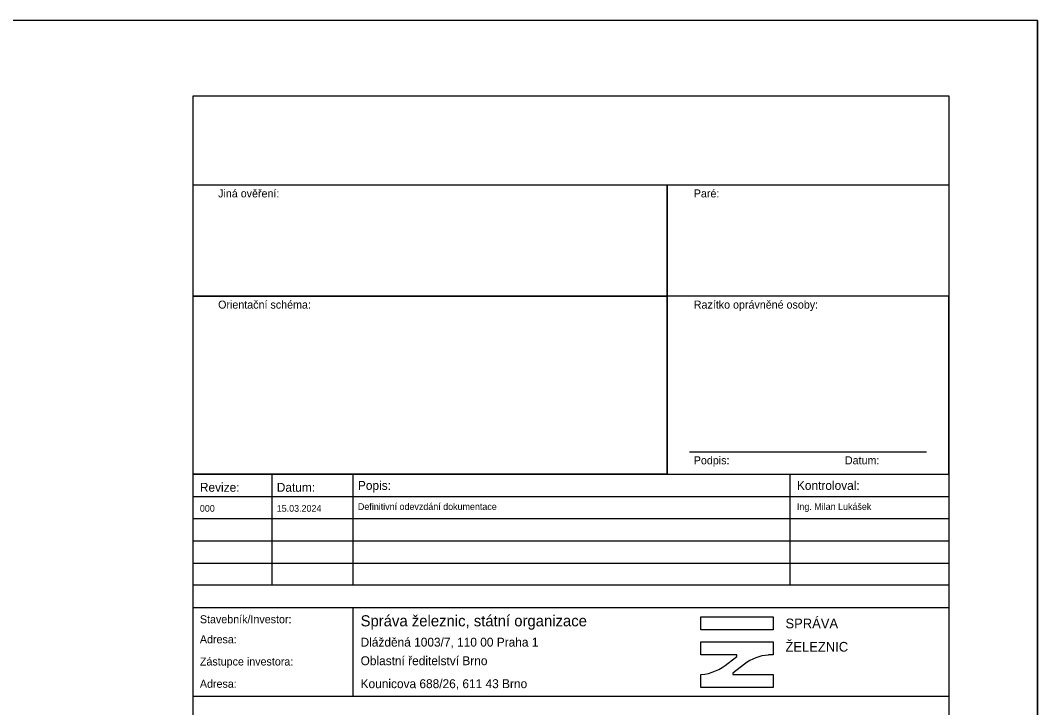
# Model space of a CAD drawing. Extents: x 2343 to 7744, y -5890 to 2050.
# Drawn here: x 6651.2 to 6880, y -5747.5 to -5593 of the extents above; entities that cross this region are included whole.
import ezdxf

# ---------------------------------------------------------------- set-up
doc = ezdxf.new("R2010")
doc.units = 0
for name, color, linetype in [('Default', 7, 'Continuous'), ('Rozpiska_Logo', 7, 'Continuous'), ('Rozpiska_pola_3', 7, 'Continuous'), ('Rozpiska_pole_1', 7, 'Continuous'), ('Rozpiska_pole_2', 7, 'Continuous'), ('Rozpiska_pole_4', 7, 'Continuous'), ('Rozpiska_pole_5', 7, 'Continuous'), ('Rozpiska_pole_6', 7, 'Continuous'), ('Vrstva 50', 7, 'Continuous')]:
    doc.layers.add(name, color=color, linetype=linetype)

msp = doc.modelspace()

# ---------------------------------------------------------------- linework, layer by layer
at = {"layer": 'Default'}
for p, q in [((6880, -5593), (6880, -5890)), ((6796.65, -5695), (6796.65, -5630))]:
    msp.add_line(p, q, dxfattribs=at)
at = {"layer": 'Rozpiska_Logo'}
for p, q in [((6810.4, -5737.47), (6812.34, -5736.01)), ((6812.34, -5736.01), (6812.34, -5735.66)), ((6814.03, -5737.74), (6811.42, -5739.76)), ((6811.42, -5739.76), (6811.42, -5740.07))]:
    msp.add_line(p, q, dxfattribs=at)
msp.add_lwpolyline([(6804.22, -5727.09), (6820.52, -5727.09), (6820.52, -5730.02), (6804.22, -5730.02)], close=True, dxfattribs=at)
for points in [[(6812.34, -5735.66), (6804.22, -5735.66), (6804.22, -5732.73), (6820.52, -5732.73), (6820.52, -5735.66), (6819.44, -5735.66)], [(6811.42, -5740.07), (6820.52, -5740.07), (6820.52, -5743), (6804.22, -5743), (6804.22, -5740.07), (6804.28, -5740.07)]]:
    msp.add_lwpolyline(points, dxfattribs=at)
for centre, radius, start, end in [((6820.18, -5745.68), 10.04, 94.2142, 127.7808), ((6803.44, -5729.58), 10.52, 274.6014, 311.4254)]:
    msp.add_arc(centre, radius, start, end, dxfattribs=at)
at = {"layer": 'Rozpiska_pola_3'}
msp.add_line((6801.65, -5690), (6855, -5690), dxfattribs=at)
at = {"layer": 'Rozpiska_pole_1'}
msp.add_lwpolyline([(6690, -5610), (6860, -5610), (6860, -5875), (6690, -5875)], close=True, dxfattribs=at)
at = {"layer": 'Rozpiska_pole_2'}
for points in [[(6690, -5630), (6796.65, -5630), (6796.65, -5655), (6690, -5655)], [(6796.65, -5630), (6860, -5630), (6860, -5655), (6796.65, -5655)], [(6690, -5655), (6796.65, -5655), (6796.65, -5695), (6690, -5695)], [(6860, -5655), (6796.65, -5655), (6796.65, -5695), (6860, -5695)]]:
    msp.add_lwpolyline(points, close=True, dxfattribs=at)
at = {"layer": 'Rozpiska_pole_4'}
for p, q in [((6707.78, -5720), (6707.78, -5695)), ((6726.05, -5720), (6726.05, -5695)), ((6824.3, -5720), (6824.3, -5695)), ((6690, -5700), (6860, -5700)), ((6690, -5705), (6860, -5705)), ((6690, -5710), (6860, -5710)), ((6690, -5715), (6860, -5715))]:
    msp.add_line(p, q, dxfattribs=at)
msp.add_lwpolyline([(6690, -5695), (6860, -5695), (6860, -5720), (6690, -5720)], close=True, dxfattribs=at)
at = {"layer": 'Rozpiska_pole_5'}
msp.add_line((6726.05, -5745), (6726.05, -5725), dxfattribs=at)
msp.add_lwpolyline([(6690, -5725), (6860, -5725), (6860, -5745), (6690, -5745)], close=True, dxfattribs=at)
at = {"layer": 'Vrstva 50'}
msp.add_lwpolyline([(5620, -5890), (6880, -5890), (6880, -5593), (5620, -5593)], close=True, dxfattribs=at)

# ---------------------------------------------------------------- texts
at = {"layer": 'Rozpiska_pola_3'}
for s, p in [('Paré:', (6802.65, -5632.8)), ('Razítko oprávněné osoby:', (6802.65, -5657.8)), ('Podpis:', (6802.65, -5692.8)), ('Datum:', (6836.65, -5692.8))]:
    msp.add_text(s, height=1.8, dxfattribs=at).set_placement(p)
at = {"layer": 'Rozpiska_pole_2'}
for s, p in [('Jiná ověření:', (6695.65, -5632.8)), ('Orientační schéma:', (6695.65, -5657.8))]:
    msp.add_text(s, height=1.8, dxfattribs=at).set_placement(p)
at = {"layer": 'Rozpiska_pole_4'}
for s, height, p in [('Revize:', 2, (6691.55, -5698.97)), ('Datum:', 2, (6708.84, -5698.97)), ('Popis:', 2, (6727.1, -5698.55)), ('Kontroloval:', 2, (6825.85, -5698.55)), ('000', 1.5, (6691.55, -5703.47)), ('15.03.2024', 1.5, (6708.84, -5703.47)), ('Definitivní odevzdání dokumentace', 1.5, (6727.1, -5703.05)), ('Ing. Milan Lukášek', 1.5, (6825.85, -5703.05))]:
    msp.add_text(s, height=height, dxfattribs=at).set_placement(p)
at = {"layer": 'Rozpiska_pole_5'}
for s, height, p in [('Stavebník/Investor:', 1.8, (6691.55, -5728.53)), ('Správa železnic, státní organizace', 2.5, (6727.7, -5729.23)), ('Adresa:', 1.8, (6691.55, -5733.03)), ('Zástupce investora:', 1.8, (6691.55, -5738.03)), ('Adresa:', 1.8, (6691.55, -5743.03))]:
    msp.add_text(s, height=height, dxfattribs=at).set_placement(p)
at = {"layer": 'Rozpiska_pole_6'}
for s, height, p in [('SPRÁVA', 2.183, (6823.27, -5729.67)), ('Dlážděná 1003/7, 110 00 Praha 1', 2, (6727.7, -5733.78)), ('ŽELEZNIC', 2.183, (6823.27, -5734.91)), ('Oblastní ředitelství Brno', 2, (6727.7, -5737.96)), ('Kounicova 688/26, 611 43 Brno', 2, (6727.7, -5743.12))]:
    msp.add_text(s, height=height, dxfattribs=at).set_placement(p)

doc.saveas('drawing.dxf')
